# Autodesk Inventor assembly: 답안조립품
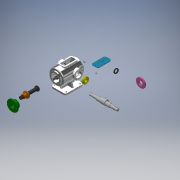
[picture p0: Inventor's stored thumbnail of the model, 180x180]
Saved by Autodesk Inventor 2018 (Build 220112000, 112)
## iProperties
Created: 2021-11
Part Number: 답안조립품
Document SubType Name: Assembly
Designer: 1class 3
Author: 1class 3
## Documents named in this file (14)
- C:\Users\1class 3\Desktop\711106v1045\답안조립품.iam
- C:\Users\1class 3\Desktop\711106v1045\본체.ipt
- C:\Users\1class 3\Desktop\711106v1045\베어링 6205.ipt
- 베어링 6205.ipt
- C:\Users\1class 3\Desktop\711106v1045\볼트 M4x0.7.ipt
- C:\Users\1class 3\Desktop\711106v1045\부시.ipt
- C:\Users\1class 3\Desktop\711106v1045\상부커버.ipt
- C:\Users\1class 3\Desktop\711106v1045\슬라이드 커버.ipt
- C:\Users\1class 3\Desktop\711106v1045\슬라이드.ipt
- C:\Users\1class 3\Desktop\711106v1045\오일실.ipt
- 오일실.ipt
- C:\Users\1class 3\Desktop\711106v1045\육각머리볼트 M4.ipt
- C:\Users\1class 3\Desktop\711106v1045\축 커버.ipt
- C:\Users\1class 3\Desktop\711106v1045\편심축.ipt
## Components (1 placed, 1 different names)
1. M4x0.7:1
